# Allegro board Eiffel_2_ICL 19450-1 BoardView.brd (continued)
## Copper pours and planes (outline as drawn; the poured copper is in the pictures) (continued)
3D3V_S5 on BOTTOM: 47.04,85.98 49.25,85.98 49.5,85.72 49.5,82.88 49.28,82.65 46.99,82.65 46.96,82.68 46.96,85.9 ; 1 cut-out
3D3V_S5 on BOTTOM: 197.71,26.66 198.63,26.66 200.13,25.16 200.13,24.4 201.21,23.31 201.21,22.05 201.01,21.84 201.01,20.05 200.8,19.85 199.11,19.85 198.8,20.16 198.8,22.68 197.56,23.92 197.56,26.5
3D3V_S5 on BOTTOM: 227.23,101.93 228.24,101.93 228.32,101.85 228.32,101.3 228.31,101.28 228.31,98.98 226.8,97.47 226.8,96.82 226.35,96.37 226.35,95.54 226.13,95.32 225.32,95.32 224.89,94.89 223.7,94.89 223.65,94.94 223.65,95.62 223.64,95.62 223.64,96.58 223.81,96.74 225.42,96.74 225.87,97.19 225.87,97.77 227.06,98.97 227.06,101.76 ; 6 cut-outs
3D3V_S5 on BOTTOM: 213.72,9.53 215.32,9.53 215.39,9.45 215.39,8.31 215.11,8.03 213.72,8.03 213.61,8.13 213.61,9.42
3D3V_S5 on BOTTOM: 246.92,95.38 247.25,95.38 247.97,94.65 261.71,94.65 262.28,94.08 262.28,44.91 262.27,44.9 262.27,34.15 261.65,33.53 260.22,33.53 259.66,32.96 259.23,32.96 258.99,33.2 258.99,33.74 259.5,34.26 259.5,90.81 258.14,92.17 246.42,92.17 245.25,93.34 245.25,93.7
3D3V_S5 on BOTTOM: 184.78,11.24 185.92,11.24 186.08,11.08 186.08,9.43 187.05,8.45 196.47,8.45 197.19,7.73 197.19,6.26 197.05,6.13 196.47,6.13 196.31,5.97 196.31,5.19 196.25,5.13 189.22,5.13 187.21,7.13 185.15,7.13 184.62,7.66 184.62,11.08 ; 1 cut-out
3D3V_S5 on BOTTOM: 85.92,7.74 86.73,7.74 86.82,7.65 86.82,7.21 86.82,7.21 86.82,7.01 86.73,6.92 84.59,6.92 83.81,6.14 83.81,5.79 84.06,5.54 84.06,4.14 83.67,3.75 82.72,3.75 82.17,3.21 77.14,3.21 77.04,3.31 77.04,6.77 77.18,6.91 80.25,6.91 80.25,6.91 81.65,6.91 81.86,7.12 83.51,7.12 83.67,7.28 83.67,7.61 83.8,7.74 85.92,7.74 ; 7 cut-outs
3D3V_S5 on L3: 181.02,31.63 181.02,31.72 181.94,32.64 184.8,32.64 185.34,32.1 185.34,31.6 185.59,31.34 189.13,31.34 189.14,31.34 190.29,31.34 194.18,27.44 199.48,27.44 200.11,26.82 203.17,26.82 203.59,26.4 203.59,25.3 203.41,25.13 195,25.13 194.49,25.64 193.98,25.64 193.32,24.98 189.61,24.98 188.95,25.64 188.11,25.64 186.63,27.12 182.14,27.12 182.02,27.24 182.02,28.57 182.04,28.59 182.04,29.9 181.14,29.9 180.97,30.07 180.97,31.58
3D3V_S5 on L3: 191.64,20.49 192.37,19.75 192.37,19.3 193.03,18.64 194.1,18.64 194.69,18.05 194.69,16.77 194.51,16.59 192.34,16.59 192.15,16.78 192.15,17.33 191.01,18.47 186.45,18.47 185.9,17.92 185.82,17.92 185.73,17.84 185.73,16.75 183.37,14.39 178.64,14.39 178.34,14.69 176.09,14.69 175.98,14.8 175.98,17.15 176.07,17.24 176.9,17.24 177.18,16.96 178.77,16.96 179.11,16.62 181.25,16.62 181.83,17.2 181.83,17.96 184.37,20.49
3D3V_S5 on L3: 104.73,49.6 104.7,49.57 104.71,49.56 104.71,48.67 102.82,46.78 100.69,46.78 97.93,44.02 97.93,39.87 100,37.8 100,36.4 99.83,36.23 93.4,36.23 91.58,38.05 91.58,41.66 92.12,42.2 92.12,45.24 91.93,45.43 91.93,64.81 92.19,65.07 94.47,65.07 95.15,64.39 95.15,61.96 94.78,61.58 94.78,52.94 95.52,52.2 104.44,52.2 104.73,51.91
3D3V_S5 on L3: 205.33,22.6 205.33,19.13 205.11,18.91 201.38,18.91 200.17,20.11 200.17,21.39 200.31,21.53 201.1,21.53 201.29,21.71 201.29,23.06 201.49,23.27 204.66,23.27
3D3V_S5 on L3: 243.19,99.44 248.1,94.54 248.1,94 246.94,92.83 246.49,92.83 238.97,100.35 230.26,100.35 230.17,100.44 227.42,100.44 227.09,100.77 227.09,102.91 227.29,103.12 241.27,103.12 243.19,101.2
3D3V_S5 on L4: 202.26,26.63 203.82,26.63 204.9,25.54 204.9,22.26 204.77,22.13 203.39,22.13 202.19,23.33 202.19,26.56
3D3V_S5 on L4: 165.32,21.34 178.36,21.34 178.51,21.19 178.51,16.74 179.89,15.36 179.89,14.56 179.56,14.24 178.88,14.24 178.21,14.91 176.1,14.91 175.89,15.12 175.89,17.59 175.67,17.81 165.43,17.81 165.05,18.19 165.05,21.06
3D3V_S5 on L4: 261.14,34.27 261.75,33.66 261.75,7.72 255.76,1.73 233.71,1.73 233.5,1.95 233.5,3.5 233.96,3.96 249.51,3.96 250.84,5.29 255.25,5.29 258.98,9.02 258.98,33.42 259.83,34.27
AUD_AGND on TOP: 27.05,79.12 28.07,79.12 28.19,78.99 28.19,76.53 28.88,75.84 28.88,73.76 28.83,73.71 27.93,73.71 27.91,73.73 27.91,74.58 26.8,75.69 26.8,78.87 ; 5 cut-outs
AUD_AGND on TOP: 29.53,69.06 29.71,69.06 29.74,69.04 29.74,68.08 29,67.34 27.08,67.34 27.06,67.33 26.76,67.33 26.43,66.99 26.43,65.75 26.61,65.56 26.61,64.88 26.78,64.71 27.78,64.71 28.01,64.94 28.01,65.22 28.06,65.27 28.89,65.27 28.97,65.2 28.97,63.47 28.83,63.34 27.99,63.34 27.26,64.07 25.71,64.07 25.35,64.43 25.35,66.64 26.58,67.87 27.82,67.87 28.25,68.3 28.74,68.3 29.06,67.97 29.36,67.97 29.5,68.11 29.5,69.03 ; 2 cut-outs
AUD_AGND on BOTTOM: 28.78,76.68 29.87,76.68 31.03,75.53 33.3,75.53 33.46,75.37 34.86,75.37 34.99,75.24 34.99,74.73 34.75,74.49 28.99,74.49 28.71,74.22 28.08,74.22 27.98,74.31 27.98,74.33 27.5,74.82 27.5,76 27.58,76.08 28.18,76.08 28.61,76.51 ; 10 cut-outs
AUD_AGND on L2GND: 27.64,82.15 38.26,82.15 38.36,82.05 38.36,78.35 38.01,77.99 36.71,77.99 36.64,77.98 36.57,77.94 36.4,77.76 36.35,77.7 36.34,77.62 36.34,77.03 34.87,75.56 34.83,75.49 34.81,75.42 34.81,74.73 34.47,74.38 29.05,74.38 28.98,74.36 28.92,74.32 28.71,74.11 28.67,74.05 28.65,73.98 28.65,69.57 28.67,69.5 28.71,69.44 29.01,69.13 29.08,69.09 29.15,69.08 29.22,69.09 29.28,69.13 29.66,69.13 29.68,69.12 29.68,68.07 29.65,68.05 29.63,68.03 28.94,67.34 26.83,67.34 26.76,67.33 26.69,67.29 26.46,67.05 26.42,66.99 26.41,66.92 26.41,65.86 26.42,65.78 26.46,65.72 26.61,65.58 26.67,65.53 26.74,65.52 27.85,65.52 28.15,65.22 28.21,65.17 28.29,65.16 28.78,65.16 28.9,65.03 28.9,63.5 28.74,63.34 27.95,63.34 27.31,63.98 27.25,64.02 27.18,64.03 22.73,64.03 22.68,64.08 22.68,66.26 22.66,66.33 22.62,66.39 20.26,68.75 20.26,71.4 21.56,72.7 21.6,72.76 21.61,72.83 21.61,76.13
AUD_AGND on L2GND: 14.57,51.21 18.51,51.21 18.93,50.79 18.93,49.15 18.94,49.08 18.98,49.02 21.89,46.11 21.89,38.77 20.67,37.55 17.17,37.55 17.1,37.53 17.04,37.49 16.7,37.16 14.25,37.16 13.91,37.49 13.91,39.47 13.9,39.55 13.86,39.61 13.26,40.2 13.2,40.24 13.13,40.26 11.98,40.26 10.93,41.3 10.93,42.34 10.92,42.42 10.88,42.48 9.6,43.75 9.6,45.14 9.82,45.36 9.86,45.42 9.87,45.49 9.87,48.06 9.86,48.13 9.82,48.19 9.49,48.52 9.49,50.15 9.89,50.55 13.84,50.55 13.91,50.57 13.97,50.61
AUD_AGND on L5GND: outline of 81 points within 9.32,37.3 37.3,81.38
AUD_SPK_L+ on TOP: 31.18,66.72 31.31,66.72 31.36,66.67 31.36,65.94 30.13,64.71 30.13,61.8 29.97,61.64 28.86,61.64 28.81,61.69 28.81,62.48 29.29,62.96 29.29,64.83
AUD_SPK_L+ on BOTTOM: 28.25,62.57 29.66,62.57 29.81,62.42 29.81,61.82 29.57,61.58 28.78,61.58 27.64,60.44 27.64,60.43 27.36,60.43 26.82,60.97 26.82,61.14
AUD_SPK_L+ on BOTTOM: 12.24,30.89 12.45,30.89 13.08,30.25 13.08,30.12 12.27,29.31 11.46,29.31 8.3,26.16 6.39,26.16 5.77,25.54 5.77,25.54 5.77,24.54 5.69,24.47 5.69,23.76 5.69,23.76 5.69,21.61 4.62,20.54 4.62,19.05 4.57,19.01 3.66,19.01 3.63,19.04 3.63,21.36 4.47,22.2 4.47,26.07 5.77,27.37 7.99,27.37 11.02,30.4 11.76,30.4 ; 1 cut-out
AUD_SPK_L+_CON on BOTTOM: 3.17,18.49 4.59,18.49 4.71,18.37 4.71,17.63 4.62,17.54 4.62,17.54 3.92,16.85 3.92,14.06 4.12,13.86 5.48,13.86 5.49,13.87 5.98,13.87 6.03,13.82 6.03,13.15 6,13.12 3.35,13.12 3.08,13.39 3.08,18.39 ; 1 cut-out
AUD_SPK_L- on TOP: 31.41,65.85 31.63,65.85 31.66,65.82 31.66,61.83 31.51,61.69 30.51,61.69 30.36,61.83 30.36,64.8
AUD_SPK_L- on BOTTOM: 30.19,62.52 31.24,62.52 31.43,62.33 31.43,61.64 30.18,60.38 29.36,60.38 28.55,59.58 28.22,59.58 27.79,60.01 27.79,60.23 28.81,61.25 29.8,61.25 30.11,61.56 30.11,62.45
AUD_SPK_L- on BOTTOM: 13.18,30 13.41,30 14.02,29.39 14.02,29.16 12.7,27.84 11.55,27.84 9.64,25.92 9.64,25.92 8.46,24.74 8.46,22.34 5.85,19.73 5.85,19.09 5.81,19.04 5.02,19.04 4.95,19.11 4.95,20.38 7.14,22.57 7.14,24.27 6.96,24.45 6.96,25.53 7.3,25.87 8.18,25.87 11.46,29.16 12.34,29.16
AUD_SPK_L-_CON on BOTTOM: 5.04,18.49 5.75,18.49 5.83,18.41 5.83,14.85 5.93,14.75 5.97,14.75 6.02,14.71 6.02,14.14 5.97,14.08 4.37,14.08 4.25,14.21 4.25,14.87 4.26,14.88 4.26,16.63 4.96,17.33 4.96,18.41 ; 1 cut-out
AUD_SPK_R+ on TOP: 32.31,66.67 32.48,66.67 35.08,64.08 35.08,61.83 34.97,61.72 33.75,61.72 33.54,61.92 33.54,64.71 32.27,65.97 32.27,66.64
AUD_SPK_R+ on BOTTOM: 16.42,28.66 16.45,28.66 17.3,27.81 17.3,27.74 16.18,26.62 16.18,23.96 12.77,20.55 11.24,20.55 10.51,19.82 9.28,19.82 9.25,19.86 9.25,20.68 9.37,20.8 9.77,20.8 10.6,21.64 11.93,21.64 12.66,22.36 12.66,22.96 13.92,24.22 13.92,26.16 ; 1 cut-out
AUD_SPK_R+ on BOTTOM: 34,62.64 34.32,62.64 34.32,62.63 34.8,62.63 34.93,62.51 34.93,60.89 31.59,57.55 30.96,58.19 30.96,58.27 30.99,58.27 33.86,61.15 33.86,62.5
AUD_SPK_R+_CON on BOTTOM: 9.37,19.33 10.1,19.33 10.17,19.25 10.17,15.7 9.67,15.19 7.34,15.19 7.23,15.31 7.23,15.81 7.34,15.92 8.97,15.92 9.3,16.25 9.3,19.25
AUD_SPK_R- on TOP: 32,65.89 32.19,65.89 33.33,64.74 33.33,61.87 33.15,61.68 32.43,61.68 32.42,61.69 32.06,61.69 31.94,61.81 31.94,65.84
AUD_SPK_R- on BOTTOM: 15.43,29.43 15.54,29.43 16.18,28.79 16.18,28.68 13.61,26.11 11.87,26.11 11.51,25.75 11.51,22 11.36,21.85 10.54,21.85 9.63,20.94 9.12,20.94 9.04,20.85 9.04,19.87 8.99,19.82 8.08,19.82 8,19.89 8,21.45 8.49,21.94 8.51,21.94 10.11,23.53 10.11,25.42 10.1,25.43 10.1,26.2 11.57,27.67 13.67,27.67
AUD_SPK_R- on BOTTOM: 32.44,62.63 33.33,62.63 33.35,62.6 33.35,61.1 30.92,58.67 30.68,58.43 30.43,58.43 29.95,58.91 29.95,59.18 32.32,61.54 32.32,62.5
AUD_SPK_R-_CON on BOTTOM: 8.11,19.32 8.92,19.32 8.98,19.26 8.98,18.42 8.99,18.42 8.99,16.27 8.85,16.14 7.33,16.14 7.22,16.24 7.22,16.8 7.28,16.85 7.96,16.85 8.08,16.97 8.08,19.29
LED_GND on TOP: 17.32,37.08 21.63,37.08 21.82,36.89 21.82,34.22 21.29,33.69 21.3,33.68 21.3,33.11 21.23,33.04 20.74,33.04 20.05,33.74 18.14,33.74 18.08,33.8 18.08,34.05 17.79,34.33 16.35,34.33 16.11,34.57 16.11,34.56 14.8,34.56 14.61,34.37 14,34.37 13.86,34.51 13.86,36.18 14.43,36.74 16.99,36.74 ; 12 cut-outs
LED_GND on L3: 16.31,23.73 20.59,23.73 20.75,23.89 20.75,24.94 19.94,25.76 19.94,27.52 20.96,28.55 22.53,28.55 22.83,28.25 22.83,28.2 23.1,27.93 25.09,27.93 25.49,28.33 25.49,30.07 26.07,30.65 26.07,31.95 25.04,32.98 25.04,35.38 23.76,36.66 14.63,36.66 14.34,36.36 14.34,33.98 12.47,32.11 12.47,27.57
M_VREF_CA_DIMMB on BOTTOM: 240.33,34.95 241.93,34.95 241.97,34.92 241.97,32.94 241.72,32.69 239.34,32.69 239.14,32.49 238.41,32.49 238.16,32.24 238.16,31.95 238.08,31.87 237.59,31.87 237.55,31.92 237.55,32.6 238.26,33.32 239.62,33.32 240.12,33.82 240.12,34.74 ; 1 cut-out
M_VREF_DQ_DIMMA on BOTTOM: 255.16,35.99 255.87,35.99 255.94,35.91 255.94,35.87 255.92,35.85 255.92,35.34 256.04,35.23 256.34,35.23 256.54,35.02 256.54,33.77 256.32,33.55 255.59,33.55 254.9,32.86 253.65,32.86 253.41,32.63 252.82,32.63 252.78,32.58 252.49,32.58 252.49,33.52 254.94,33.52 255.07,33.65 255.07,35.89 ; 2 cut-outs
MCT1 on BOTTOM: 60.12,59.32 61.19,59.32 61.21,59.3 64.92,59.3 66.82,57.4 68.81,57.4 68.81,57.4 68.87,57.34 68.87,56.89 69.04,56.71 70.54,56.71 70.71,56.87 70.71,57.28 70.84,57.4 74.43,57.4 74.73,57.1 74.73,54.05 74.54,53.87 60.43,53.87 59.95,54.35 59.95,59.16 ; 7 cut-outs
Net_2 on TOP: 158.83,65.49 164.82,65.49
Net_3 on TOP: 196.28,65.49 202.27,65.49
Net_4 on TOP: 158.83,35.57 164.82,35.57
Net_5 on TOP: 196.28,35.57 202.27,35.57
Net_6 on TOP: 232.12,104.54 244.82,104.54 244.82,103.94 244.82,103.94 244.82,93.44 232.11,93.44 232.11,103.94 232.11,103.94 232.11,104.53
Net_22 on BOTTOM (solid shape): outline of 231 points within 158.32,32.07 165.32,39.07
Net_23 on BOTTOM (solid shape): outline of 231 points within 195.77,32.07 202.77,39.07
Net_24 on BOTTOM (solid shape): outline of 230 points within 195.77,61.99 202.77,68.99
Net_25 on BOTTOM (solid shape): outline of 230 points within 158.32,61.99 165.32,68.99
PWR_1D05V on BOTTOM: 123.46,38.76 125.25,38.76 125.32,38.69 125.32,37.99 125.4,37.91 126.55,37.91 126.7,38.07 126.7,38.22 126.76,38.28 127.52,38.28 127.58,38.22 127.58,36.67 127.08,36.17 127.03,36.13 125.53,36.13 125.3,35.89 125.3,35.88 124.37,34.96 123.64,34.96 123.54,35.05 123.54,35.62 123.3,35.86 123.3,38.6 ; 5 cut-outs
PWR_1D8V on TOP: 126.83,38.91 128.92,38.91 130.9,36.93 130.9,35.21 131.21,34.9 131.57,34.9 132.03,34.43 132.03,32.92 132.03,32.92 127.97,32.92 127.91,32.98 127.53,32.98 127.35,33.16 127.35,36.02 127.14,36.23 126.89,36.23 126.68,36.43 126.68,38.76 ; 4 cut-outs
PWR_1D8V on BOTTOM: 127.94,36.59 131.77,36.59 132.03,36.33 132.03,32.62 131.93,32.52 127.32,32.52 127.23,32.6 127.23,35.89 ; 5 cut-outs
PWR_1D8V_PH on TOP: 127.04,43.29 131.35,43.29 132.72,41.92 133.93,41.92 134.58,41.26 134.58,40.22 134.71,40.09 136.75,40.09 136.79,40.14 137.62,40.14 137.79,39.97 137.79,39.16 137.75,39.12 133.89,39.12 133.89,39.63 133.8,39.72 132.5,39.72 131.9,40.31 126.83,40.31 126.67,40.48 126.67,42.92
PWR_2D5V_VIN on BOTTOM: 258.12,36.39 258.97,36.39 259.05,36.3 259.05,34.33 258.88,34.16 258.88,30.29 258.44,29.84 258.44,29.62 258.45,29.62 258.45,28.62 258.07,28.24 258.07,26.7 257.35,25.98 257.35,24.31 257.61,24.05 260.63,24.05 260.76,23.93 260.76,21.06 260.75,21.05 257.03,21.05 256.59,21.49 256.59,26.28 256.39,26.49 256.39,28.21 256.55,28.37 257,28.37 257.26,28.63 257.26,34.08 258.02,34.84 258.02,36.28 ; 2 cut-outs
PWR_2D5V_VPP on BOTTOM: 256.7,20.85 258.7,20.85 258.88,20.68 258.88,17.83 259.44,17.27 259.97,17.27 259.99,17.25 259.99,13.94 259.79,13.74 257.07,13.74 256.92,13.9 256.92,14.67 257.26,15.02 257.26,18.57 256.59,19.25 256.59,20.47 256.6,20.48 256.6,20.75 ; 7 cut-outs
PWR_3D3V on TOP: 104.85,57.78 110.59,57.78 110.7,57.67 110.7,53.38 110.67,53.38 110.54,53.24 104.22,53.24 103.82,53.65 103.82,57.17 104.41,57.76 104.83,57.76
PWR_3D3V on BOTTOM: 102.49,57.97 110.35,57.97 110.6,57.72 110.6,54.95 109.69,54.05 109.69,52.66 109.67,52.64 102.87,52.64 102.69,52.82 102.69,54.7 102.3,55.09 102.3,57.78 ; 2 cut-outs
PWR_3D3V_LDO3 on TOP: 100.5,80.94 101.58,80.94 103.21,79.32 103.21,78.63 102.95,78.37 100.26,78.37 100.18,78.45 100.18,79.36 100.36,79.54 100.36,80.8 ; 2 cut-outs
PWR_3D3V_LG2 on BOTTOM: 103.31,74.76 103.77,74.76 104.54,73.99 104.54,73.68 104.31,73.45 103.93,73.45 103.53,73.86 103.31,73.86 103.26,73.9 103.26,74.72
PWR_3D3V_PH2 on TOP: 108.5,65.78 111.74,65.78 111.79,65.73 111.79,64.01 112.01,63.78 113.11,63.78 113.77,63.12 113.77,61.16 113.61,61.01 112.52,61.01 112.34,61.19 111.63,61.19 111.35,60.91 111.35,59.72 110.44,58.8 106.17,58.8 105.99,58.98 105.99,61.79 106.06,61.86 107.48,61.86 108.43,62.81 108.43,65.71
PWR_5V on TOP: 92.89,58.93 95.18,58.93 96.21,57.9 101.69,57.9 102.06,57.52 102.06,53.36 101.74,53.04 97.61,53.04 97.51,52.93 97.51,52.17 97.43,52.1 92.82,52.1 92.49,52.43 92.49,56.5 92.52,56.53 92.52,58.79 92.67,58.93 92.89,58.93 ; 1 cut-out
PWR_5V on BOTTOM: 93.55,59.84 94.18,59.84 94.31,59.72 94.31,59.44 94.41,59.33 96.28,59.33 96.7,58.92 96.7,52.45 96.3,52.06 93.55,52.06 93.43,52.18 93.43,59.73
PWR_5V_HG1 on BOTTOM: 100.57,75.17 101.38,75.17 101.49,75.17 101.5,75.16 101.5,74.96 101.42,74.88 101.27,74.88 100.02,73.64 99.64,73.64 99.45,73.82 99.45,74.18 99.6,74.33 100.11,74.33 100.49,74.71 100.49,75.09
PWR_5V_LG1 on BOTTOM: 101.69,74.75 101.87,74.75 101.89,74.72 101.89,73.81 101.54,73.46 101.54,72.62 101.45,72.53 99.47,72.53 99.31,72.69 99.31,73.1 99.6,73.39 100.61,73.39 101.69,74.47 101.69,74.74
PWR_5V_PH1 on TOP: 101.66,66.25 104.66,66.25 104.73,66.17 104.73,62.94 103.28,61.49 103.28,59.28 102.92,58.92 98.05,58.92 97.64,59.33 97.64,63.82 97.67,63.85 99.34,63.85 99.36,63.83 99.36,62.66 99.39,62.64 100.84,62.64 101.64,63.44 101.64,66.23
PWR_DCBATOUT_1D8V on TOP: 137.44,42.34 139.27,42.34 139.27,41.76 140.37,40.66 140.37,37.68 139.96,37.27 133.89,37.27 133.85,37.31 133.85,38.83 133.9,38.87 137.77,38.87 137.9,39 137.9,40.2 137.81,40.29 137.34,40.29 137.33,40.3 137.33,42.22 ; 2 cut-outs
PWR_DCBATOUT_1D8V on BOTTOM: 138.05,41.06 140,41.06 140.25,40.81 140.25,39.72 140.34,39.62 140.34,37.63 140,37.28 138.28,37.28 137.88,37.68 137.88,40.89
PWR_DCBATOUT_3D3V on TOP: 113.18,73.38 116.08,73.38 116.08,73.38 116.21,73.25 116.21,64.35 117.21,63.35 117.21,59.83 117.17,59.79 114.19,59.79 114.15,59.83 114.15,63.04 112.83,64.36 112.83,73.03 ; 2 cut-outs
PWR_DCBATOUT_5V on TOP: 98.9,72.42 101.58,72.42 101.58,68.79 101.8,68.57 102.44,68.57 102.57,68.44 102.57,66.97 102.4,66.8 100.76,66.8 100.59,66.63 100.59,64.17 100.51,64.09 97.14,64.09 97.02,64.22 97.02,70.09 97.14,70.21 98.46,70.21 98.68,70.43 98.68,72.2
PWR_DCBATOUT_5V on BOTTOM: 97.16,72.11 98.44,72.11 98.48,72.07 98.48,71.17 99.92,69.72 99.92,67.87 99.82,67.77 97.08,67.77 96.88,67.97 96.88,71.83 ; 2 cut-outs
PWR_DCBATOUT_VCCAUX on TOP: 134.72,57.79 139.79,57.79 139.89,57.69 139.89,52.57 139.51,52.2 130.37,52.2 130.26,52.3 130.26,53.78 127.8,56.24 127.8,57.74 127.85,57.79 131.55,57.79 131.57,57.76 131.57,57.23 132.1,56.7 133.64,56.7
PWR_DCBATOUT_VCCAUX on BOTTOM: 134.8,57.84 139.63,57.84 139.8,57.67 139.8,52.36 139.64,52.2 134.17,52.2 134.03,52.06 132.04,52.06 132.04,54.4 132.03,54.41 132.03,55.07
PWR_DCBATOUT_VCOREA on TOP: 132.03,64.36 135.71,64.36 135.79,64.29 135.79,62.99 135.97,62.81 141.43,62.81 141.53,62.71 141.53,59.21 141.29,58.97 131.77,58.97 131.75,58.99 131.75,64.08
PWR_DCBATOUT_VCOREA on BOTTOM: 132.03,64.36 135.71,64.36 135.79,64.29 135.79,62.99 135.97,62.81 141.43,62.81 141.53,62.71 141.53,61.82 141.5,61.8 140.34,61.8 140.21,61.66 140.21,60.12 140.21,60.12 140.21,59.87 140.16,59.82 131.98,59.82 131.98,64.31
PWR_DCBATOUT_VCOREA on L4: 134.36,64.21 141.43,64.21 141.58,64.06 141.58,62.15 141.27,61.84 135.87,61.84 134.14,60.11 132.63,60.11 131.94,60.79 131.94,61.8
PWR_DCBATOUT_VCOREB on TOP: 131.85,79.02 139.78,79.02 139.98,78.82 139.98,76.17 140.13,76.02 141.5,76.02 141.5,75.11 141.43,75.03 136.19,75.03 135.79,74.63 135.79,73.91 135.64,73.76 132.03,73.76 131.83,73.96 131.83,78.99
PWR_DCBATOUT_VCOREB on BOTTOM: 131.85,79.02 141.13,79.02 141.5,78.65 141.5,75.11 141.43,75.03 136.19,75.03 135.79,74.63 135.79,73.91 135.64,73.76 132.03,73.76 131.83,73.96 131.83,78.99
PWR_DCBATOUT_VCOREB on L4: 135.23,77.07 135.23,76.22 135.37,76.08 141.26,76.08 141.37,75.97 141.37,75.43 141.21,75.27 132.54,75.27 132.46,75.35 132.46,77.19 132.5,77.23 135.08,77.23
PWR_DCBATOUT_VDDQ on BOTTOM: 238.14,89.23 238.38,89.23 238.38,83.9 238.3,83.82 233.42,83.82 233.07,84.16 233.07,84.74 232.83,84.99 230.02,84.99 229.88,85.14 228.37,85.14 228.18,85.32 228.18,88.87 228.53,89.22 238.13,89.22 ; 2 cut-outs
PWR_DMIC on TOP: 209.66,101.72 211.25,101.72 211.36,101.61 211.36,100.5 211.4,100.46 213.65,100.46 213.86,100.25 213.86,97.36 213.53,97.03 212.48,97.03 212.35,96.9 210.94,96.9 210.86,96.97 210,96.97 209.52,97.46 209.52,101.58 ; 3 cut-outs
PWR_VCCAUX_BOOT on TOP: 143.48,43.35 143.9,43.35 144.15,43.09 144.15,41.33 143.77,41.33 143.7,41.4 143.7,42.59 143.41,42.88 143.41,43.28
PWR_VCCAUX_PH on TOP: 140.42,56.29 145.87,56.29 145.94,56.22 145.94,52.71 145.58,52.35 145.58,48.94 145.59,48.93 145.59,47.57 145.39,47.37 142.2,47.37 141.89,47.06 141.89,46.04 141.82,45.98 136.63,45.98 136.56,46.04 136.56,51.35 136.85,51.64 139.61,51.64 140.15,52.18 140.15,56.02
PWR_VCCAUX_PH on BOTTOM: 140.27,57.8 144.8,57.8 144.82,57.79 145.98,57.79 146.22,57.55 146.22,51.06 145.61,50.45 145.61,47.57 145.4,47.37 143.4,47.37 141.93,45.9 136.73,45.9 136.63,46 136.63,51.44 136.93,51.74 139.64,51.74 140.38,52.48 141.02,52.48 141.76,51.74 142.39,51.74 142.39,53.32 141.97,53.74 141.59,53.74 141.55,53.69 140.3,53.69 140.27,53.72
PWR_VCORE_PHA on TOP: 142.82,67.31 145.96,67.31 146.13,67.15 146.13,62.36 146.66,61.82 146.66,58.75 146.58,58.67 143.36,58.67 142.72,59.31 142.72,62.74 142.19,63.27 136.19,63.27 136.19,65.91 136.35,66.07 136.35,66.17 142.33,66.17 142.71,66.54 142.71,67.2
PWR_VCORE_PHA on BOTTOM: 142.8,67.27 145.73,67.27 146.1,66.9 146.1,66.11 146.13,66.09 146.13,60.61 146.08,60.56 142.78,60.56 142.67,60.67 142.67,62.79 142.19,63.27 136.19,63.27 136.19,65.91 136.35,66.07 136.35,66.17 142.32,66.17 142.67,66.52 142.66,66.53 142.66,67.13
PWR_VCORE_PHB on TOP: 145.34,79.17 146.51,79.17 146.66,79.02 146.66,75.69 146.13,75.16 146.13,70.64 146.03,70.54 143.09,70.54 142.71,70.92 142.71,71.57 142.42,71.86 136.22,71.86 136.14,71.93 136.14,74.7 136.22,74.78 142.14,74.78 142.63,75.27 142.63,77 142.77,77.14 145.16,77.14 145.21,77.19 145.21,79.04
PWR_VCORE_PHB on BOTTOM: 142.75,77.17 146,77.17 146.13,77.04 146.13,71.58 146.12,71.57 146.12,70.67 145.98,70.54 143.14,70.54 142.87,70.8 142.87,71.4 142.42,71.86 136.22,71.86 136.14,71.93 136.14,74.7 136.22,74.78 142.14,74.78 142.61,75.25 142.61,77.03
PWR_VDDQ_PH on BOTTOM: 237.49,97.76 239.13,97.76 244.75,92.15 244.75,86.72 244.55,86.52 241.42,86.52 240.37,85.47 238.86,85.47 238.81,85.52 238.81,89.87 238.46,90.22 235.33,90.22 235.33,91.42 235.29,91.46 235.29,94.79 235.3,94.8 235.3,95.78 235.36,95.83 237.19,95.83 237.4,96.05 237.4,97.68
PWR_VDDQ_PH on BOTTOM: 221.71,88.49 224.01,88.49 224.17,88.33 224.17,87.1 223.95,86.89 222.49,86.89 221.66,87.72 221.66,88.45 ; 2 cut-outs
PWR_VDDQ_VLDOIN on BOTTOM: 216.57,87.61 219.24,87.61 219.34,87.51 219.34,86.41 218.82,85.88 216.38,85.88 216.35,85.91 216.35,87.39
PWR_VDDQ_VTT on BOTTOM: 214.73,90.97 216.71,90.97 217.48,90.19 217.48,89.89 217.44,89.85 216.94,89.85 216.73,89.63 216.73,89.27 216.93,89.06 218.47,89.06 218.58,88.94 218.58,88.07 218.43,87.92 216.18,87.92 216.03,87.76 216.03,86.5 215.9,86.38 214.71,86.38 214.71,87.9 214.39,88.22 213.56,88.22 213.52,88.26 213.52,89.06 213.56,89.1 214.39,89.1 214.67,89.37 214.67,90.9
PWR_VNN on BOTTOM: 112.32,39.42 113.64,39.42 113.77,39.29 113.77,36.71 113.1,36.04 113.1,35.12 113.07,35.09 109.94,35.09 109.81,35.21 109.81,37.12 110.01,37.32 111.99,37.32 112.18,37.51 112.18,39.29 ; 5 cut-outs
PWR_VNN1D05V_PHA on BOTTOM: 114.19,39.52 115.86,39.52 116.01,39.37 116.01,38.12 116.23,37.9 116.94,37.9 117.01,37.82 117.01,37.12 117.01,37.11 117.01,36.46 117.4,36.06 117.4,34.69 117.37,34.66 116.6,34.66 116.55,34.7 116.55,35.7 116.55,35.99 115.99,36.56 114.22,36.56 114.07,36.71 114.07,39.4 ; 1 cut-out
PWR_VNN1D05V_PHB on BOTTOM: 121.47,38.7 122.92,38.7 123.01,38.61 123.01,36.21 122.87,36.07 120.47,36.07 120.46,36.07 119.44,35.05 119.44,34.84 119.25,34.65 118.67,34.65 118.59,34.73 118.59,35.43 118.61,35.44 118.61,35.9 119.26,36.55 119.26,36.9 119.32,36.96 120.2,36.96 121.41,38.17 121.41,38.63 ; 2 cut-outs
PWR_VNN1D05V_VINA on BOTTOM: 117.6,32.24 117.87,32.24 117.9,32.21 117.9,30.4 117.65,30.14 117.65,28.96 117.57,28.88 116.8,28.88 116.43,29.24 115.66,29.24 115.6,29.3 115.6,30.48 116.11,30.99 117.37,30.99 117.6,31.22 117.6,32.24 ; 2 cut-outs
PWR_VNN1D05V_VINB on BOTTOM: 118.1,32.26 118.37,32.26 118.4,32.22 118.4,31.47 120,29.87 120,29.28 119.97,29.24 119,29.24 118.93,29.17 118.93,29.01 118.8,28.88 117.97,28.88 117.92,28.93 117.92,29.89 118.07,30.05 118.07,32.23 ; 2 cut-outs
SIO_AGND on BOTTOM: 75.68,20.49 81.56,20.49 81.66,20.39 81.66,18.62 81.55,18.5 76.61,18.5 76.56,18.55 76.56,19.13 76.35,19.33 75.72,19.33 75.59,19.46 75.59,20.41 ; 18 cut-outs

Small or netless copper shapes (teardrops, artwork), in the pictures only: 5 on TOP, 5 on BOTTOM

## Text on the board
Ref Des/Silkscreen Bottom: X3101:25MHZ | F3001:1.1A/6V | 1-2 | 2-3 | X1801:32.768KHZ | MFG1 | DEBUG | DEFAULT | F5501:1.1A/24V | B | A
Ref Des/Silkscreen Top: S4# | S3# | POK | X1802:38.4MHZ | F3002:1.1A/6V | F6001:2A/6V | F5701:1.1A/6V | A | D | C | B | F | Eiffel_2_ICL | 19450-1A | 348.0CW06.001A
User.9: 19450-1A
User.10: DDR | ECIO | CPU | INT | POWER | SEQUENCE | DEBUG
User.25: ByImpedance:100.0_DP@imp="100.0"|_REF_L3=("4.0/9.0(L2/L5)")|Type="DP"|_REF_L4=("4.0/9.0(L2/L5)")|_REF_L1=("4.0/10.0(L2)")|_REF_L6=("4.0/10.0(L5)") | ByImpedance:110.0_DP@imp="110.0"|_REF_L3=("3.5/13.0(L2/L5)")|Type="DP"|_REF_L4=("3.5/13.0(L2/L5)") | ByImpedance:37.5_SE@imp="37.5"|_REF_L3=("9.5(L2/L5)")|Type="SE"|_REF_L4=("9.5(L2/L5)")|_REF_L1=("8.0(L2)")|_REF_L6=("8.0(L5)") | ByImpedance:40.0_SE@imp="40.0"|_REF_L3=("8.0(L2/L5)")|Type="SE"|_REF_L4=("8.0(L2/L5)")|_REF_L1=("7.0(L2)")|_REF_L6=("7.0(L5)") | ByImpedance:42.0_SE@imp="42.0"|_REF_L3=("7.5(L2/L5)")|Type="SE"|_REF_L4=("7.5(L2/L5)")|_REF_L1=("6.5(L2)")|_REF_L6=("6.5(L5)") | ByImpedance:45.0_SE@imp="45.0"|_REF_L3=("6.5(L2/L5)")|Type="SE"|_REF_L4=("6.5(L2/L5)")|_REF_L1=("5.5(L2)")|_REF_L6=("5.5(L5)") | ByImpedance:48.0_SE@imp="48.0"|_REF_L3=("6.0(L2/L5)")|Type="SE"|_REF_L4=("6.0(L2/L5)")|_REF_L1=("5.0(L2)")|_REF_L6=("5.0(L5)") | ByImpedance:50.0_SE@imp="50.0"|_REF_L3=("5.0(L2/L5)")|Type="SE"|_REF_L4=("5.0(L2/L5)")|_REF_L1=("4.5(L2)" "15.5(L3)")|_REF_L6=("4.5(L5)" "15.5(L4)") | ByImpedance:55.0_SE@imp="55.0"|_REF_L3=("4.0(L2/L5)")|Type="SE"|_REF_L4=("4.0(L2/L5)")|_REF_L1=("3.5(L2)")|_REF_L6=("3.5(L5)") | ByImpedance:68.0_DP@imp="68.0"|_REF_L3=("8.0/4.5(L2/L5)")|Type="DP"|_REF_L4=("8.0/4.5(L2/L5)")|_REF_L1=("7.5/5.0(L2)")|_REF_L6=("7.5/5.0(L5)") | ByImpedance:70.0_DP@imp="70.0"|_REF_L3=("8.0/5.0(L2/L5)")|Type="DP"|_REF_L4=("8.0/5.0(L2/L5)")|_REF_L1=("7.0/5.0(L2)")|_REF_L6=("7.0/5.0(L5)") | ByImpedance:80.0_DP@imp="80.0"|_REF_L3=("5.0/4.0(L2/L5)" "5.5/5.0(L2/L5)" "6.0/6.0(L2/L5)")|Type="DP"|_REF_L4=("5.0/4.0(L2/L5)" "5.5/5.0(L2/L5)" "6.0/6.0(L2/L5)")|_REF_L1=("5.5/5.0(L2)")|_REF_L6=("5.5/5.0(L5)") | ByImpedance:85.0_DP@imp="85.0"|_REF_L3=("5.5/7.0(L2/L5)" "5.0/5.5(L2/L5)" "4.5/4.5(L2/L5)")|Type="DP"|_REF_L4=("5.5/7.0(L2/L5)" "5.0/5.5(L2/L5)" "4.5/4.5(L2/L5)")|_REF_L1=("5.0/6.0(L2)" "4.0/4.0(L2)")|_REF_L6=("4.0/4.0(L5)" "5.0/6.0(L5)") | ByImpedance:88.0_DP@imp="88.0"|_REF_L3=("4.0/4.5(L2/L5)")|Type="DP"|_REF_L4=("4.0/4.5(L2/L5)")|_REF_L1=("4.0/4.5(L2)")|_REF_L6=("4.0/4.5(L5)") | ByImpedance:90.0_DP@imp="90.0"|_REF_L3=("5.0/8.0(L2/L5)" "4.0/5.0(L2/L5)" "4.5/6.0(L2/L5)")|Type="DP"|_REF_L4=("5.0/8.0(L2/L5)" "4.0/5.0(L2/L5)" "4.5/6.0(L2/L5)")|_REF_L1=("4.0/5.0(L2)")|_REF_L6=("4.0/5.0(L5)") | ByImpedance:95.0_DP@imp="95.0"|_REF_L3=("4.0/6.5(L2/L5)")|Type="DP"|_REF_L4=("4.0/6.5(L2/L5)")|_REF_L1=("4.0/6.5(L2)")|_REF_L6=("4.0/6.5(L5)") | LayerIndex:nil | Source:6-1.2-10d.xls | artWorks:("_REF_L4" "_REF_L1" "_REF_L6" "_REF_L3") | gtImpOutlineUsed:BOARD GEOMETRY/PANEL_OUTLINE
User.29: Broken Plane Check,Oct 18 13:21:01 2019,3 errors | Component Overlap Check,Oct 09 15:13:09 2019,3 errors | Cross Thermal And Anti Pad Check,Oct 07 10:07:57 2019,930 errors | Diffpair Gap Check,Feb 14 23:41:55 2019,632 errors | Outline Clearance Check,Oct 17 16:07:35 2019,101 errors | Proper Pad Entry Check,Oct 20 08:53:30 2019,869 errors | Silkscreen Overlap Check,Oct 19 17:26:03 2019,639 errors | TP Violations Check,Nov 27 23:01:58 2019,1473 errors | Trace To Trace Spacing Check,Oct 18 13:19:23 2019,678 errors | Via Connectivity,Oct 18 13:20:51 2019,54 errors | Via On Moat Check,Oct 20 08:35:07 2019,Passed
User.33: 260 | + | 2-3 | F3001:1.1A/6V | F5701:1.1A/6V | X1801:24MHZ | X1802:32.768KHZ | A | B | C | D | E | c | 348.09007.00SA | EIFFEL215i-2 | MADE IN TAIWAN
User.39: POK | S3# | S4# | + | - | 1 | 260 | 1-2 | 2-3 | DEBUG | DEFAULT | F3001:1.1A/6V | F3002:1.1A/6V | F5501:1.1A/24V | F5701:1.1A/6V | F6001:2A/6V | MFG1 | OSC1:48MHZ | X1801:24MHZ | X1801:32.768KHZ | X1802:32.768KHZ | X1802:38.4MHZ | X3101:25MHZ | A | B | C | D | E | F | 18449-1A | 19450-SA | 348.0CW01.001A | 348.0CW06.00SA | Eiffel_2_ICL | MADE IN TAIWAN | PICMLU/Eiffel238i-2
User.45: Note:Refer to DRILL layer for ELLIPSE drill direction | FIGURE | FINISHED_SIZE | 8.0 | 10.0 | 16.0 | 20.0 | 28.0 | 30.0 | 34.0 | 36.0 | 38.0 | 109.0 | 113.0 | 128.0 | 42.0 | 44.0 | 46.0 | 50.0 | 54.0 | 63.0 | 65.0 | 67.0 | 86.0 | 126.0 | 158.0 | 60.0x24.0 | 87.0x24.0 | 91.0x32.0 | 95.0x40.0 | 99.0x36.0 | 156.0x32.0 | 166.0x32.0 | DRILL CHART: TOP to BOTTOM | ALL UNITS ARE IN MILS | PLATED | NON-PLATED | QTY | 337 | 2813 | 536 | 40 | 18 | 22 | 4 | 2 | 1 | 3 | 8 | This gerber is just for your reference to find the DP impedance traces in layer L1. | This gerber is just for your reference to find the DP impedance traces in layer L6. | This gerber is just for your reference to find the SE impedance traces in layer L1. | This gerber is just for your reference to find the SE impedance traces in layer L3. | This gerber is just for your reference to find the SE impedance traces in layer L4. | This gerber is just for your reference to find the SE impedance traces in layer L6. | This gerber is just for your reference to find the DP impedance traces in layer L3. | This gerber is just for your reference to find the DP impedance traces in layer L4. | DP IMPEDANCE TABLE: L1 | DP IMPEDANCE TABLE: L3 | DP IMPEDANCE TABLE: L4 | DP IMPEDANCE TABLE: L6 | SE IMPEDANCE TABLE: L1 | SE IMPEDANCE TABLE: L3 | SE IMPEDANCE TABLE: L4 | SE IMPEDANCE TABLE: L6 | * - Denotes that this Impedance | is NOT used | Model | Eiffel_2_ICL | PCB_NO | 19450 | VER. | 1A | Layer | DRILL | L1 | L2GND | L3 | TMASK | TPLACE | TSILK | TSMD | Designer | WPH-LEN | Date | 11/28/2019 | IMP(Ohm) | *37.5 | *68.0 | *40.0 | *70.0 | *42.0 | *80.0 | 80.0 | *85.0 | 45.0 | 85.0 | *48.0 | *88.0 | *50.0 | *55.0 | 90.0 | *95.0 | 100.0 | *90.0 | *100.0 | *110.0 | WIDTH(mils) | 9.5 | 7.0 | 6.5 | 7.5 | 5.5 | 5.0 | 6.0 | 4.5 | 15.5 | 4.0 | 3.5 | 7.5/5.0 | 7.0/5.0 | 5.5/5.0 | 4.0/4.0 | 5.0/6.0 | 4.0/4.5 | 4.0/5.0 | 4.0/6.5 | 4.0/10.0 | 8.0/4.5 | 8.0/5.0 | 5.0/4.0 | 6.0/6.0 | 5.5/7.0 | 5.0/5.5 | 4.5/4.5 | 5.0/8.0 | 4.5/6.0 | 4.0/9.0 | 3.5/13.0 | TYPE | SE | DP | Ref. Plane | L2 | L2/L5 | L5 | L4 | BMASK | BPLACE | BSILK | BSMD | L5GND | L6
